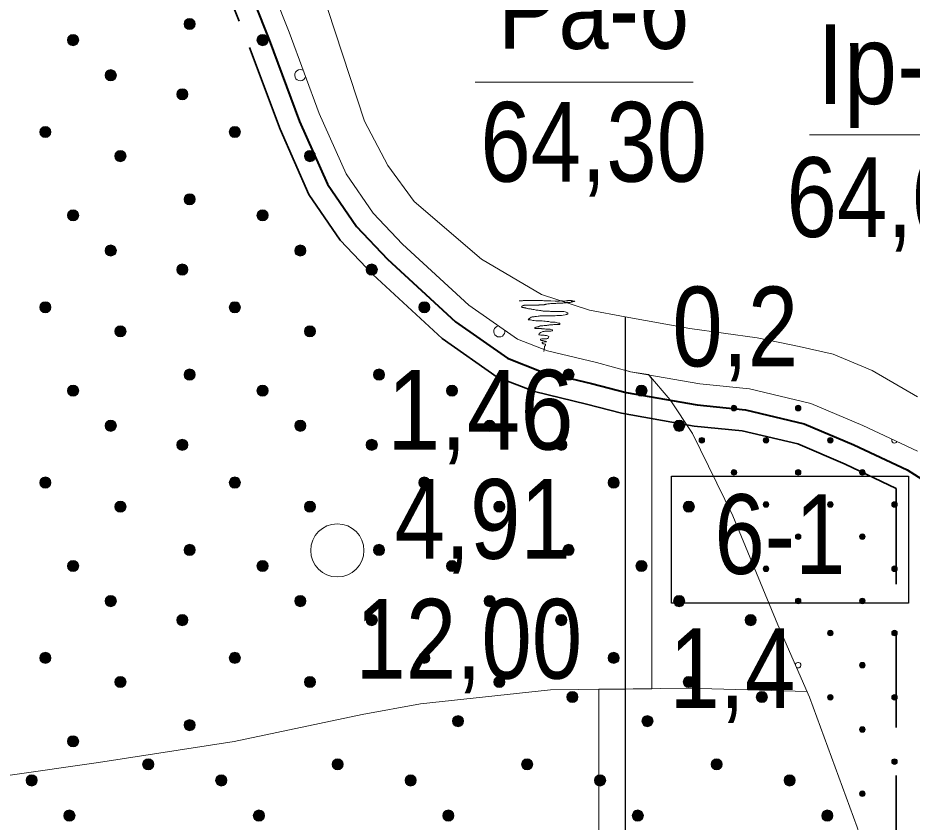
# Model space of a CAD drawing. Extents: x 640121 to 640955, y 6441885 to 6442246.
# Drawn here: x 640239.34 to 640273.01, y 6441962.4 to 6441992.66 of the extents above; entities that cross this region are included whole.
import ezdxf
from ezdxf.enums import TextEntityAlignment as Align

# ---------------------------------------------------------------- set-up
doc = ezdxf.new("R2010")
doc.units = 0
doc.header["$LTSCALE"] = 1.2
doc.linetypes.add('MEDIUM_DASHED', pattern=[4.5, 3, -1.5])
for name, color, linetype, lineweight in [('31', 7, 'Continuous', 13), ('32', 7, 'Continuous', 13), ('33', 7, 'Continuous', 13), ('35', 7, 'Continuous', 35), ('40', 7, 'Continuous', 13), ('44', 7, 'Continuous', 13), ('45', 7, 'Continuous', 13), ('47', 7, 'Continuous', 13)]:
    doc.layers.add(name, color=color, linetype=linetype, lineweight=lineweight)

msp = doc.modelspace()

# ---------------------------------------------------------------- hatches: boundary and pattern name
at = {"layer": '44'}
for points in [[(640246.016, 6441992.434, 1), (640245.596, 6441992.434, 1)], [(640241.63, 6441991.828, 1), (640241.21, 6441991.828, 1)], [(640248.763, 6441991.828, 1), (640248.343, 6441991.828, 1)], [(640243.049, 6441990.506, 1), (640242.629, 6441990.506, 1)], [(640245.742, 6441989.79, 1), (640245.322, 6441989.79, 1)], [(640240.586, 6441988.371, 1), (640240.166, 6441988.371, 1)], [(640247.719, 6441988.371, 1), (640247.299, 6441988.371, 1)], [(640243.413, 6441987.463, 1), (640242.993, 6441987.463, 1)], [(640250.546, 6441987.463, 1), (640250.126, 6441987.463, 1)], [(640246.016, 6441985.838, 1), (640245.596, 6441985.838, 1)], [(640241.63, 6441985.232, 1), (640241.21, 6441985.232, 1)], [(640248.763, 6441985.232, 1), (640248.343, 6441985.232, 1)], [(640243.049, 6441983.91, 1), (640242.629, 6441983.91, 1)], [(640250.182, 6441983.91, 1), (640249.762, 6441983.91, 1)], [(640245.742, 6441983.194, 1), (640245.322, 6441983.194, 1)], [(640252.875, 6441983.194, 1), (640252.455, 6441983.194, 1)], [(640240.586, 6441981.775, 1), (640240.166, 6441981.775, 1)], [(640247.719, 6441981.775, 1), (640247.299, 6441981.775, 1)], [(640254.852, 6441981.775, 1), (640254.432, 6441981.775, 1)], [(640243.413, 6441980.867, 1), (640242.993, 6441980.867, 1)], [(640250.546, 6441980.867, 1), (640250.126, 6441980.867, 1)], [(640246.016, 6441979.242, 1), (640245.596, 6441979.242, 1)], [(640253.149, 6441979.242, 1), (640252.729, 6441979.242, 1)], [(640260.282, 6441979.242, 1), (640259.862, 6441979.242, 1)], [(640241.63, 6441978.636, 1), (640241.21, 6441978.636, 1)], [(640248.763, 6441978.636, 1), (640248.343, 6441978.636, 1)], [(640255.896, 6441978.636, 1), (640255.476, 6441978.636, 1)], [(640263.029, 6441978.636, 1), (640262.609, 6441978.636, 1)], [(640243.049, 6441977.314, 1), (640242.629, 6441977.314, 1)], [(640250.182, 6441977.314, 1), (640249.762, 6441977.314, 1)], [(640257.315, 6441977.314, 1), (640256.895, 6441977.314, 1)], [(640264.448, 6441977.314, 1), (640264.028, 6441977.314, 1)], [(640245.742, 6441976.598, 1), (640245.322, 6441976.598, 1)], [(640252.875, 6441976.598, 1), (640252.455, 6441976.598, 1)], [(640260.008, 6441976.598, 1), (640259.588, 6441976.598, 1)], [(640240.586, 6441975.179, 1), (640240.166, 6441975.179, 1)], [(640247.719, 6441975.179, 1), (640247.299, 6441975.179, 1)], [(640254.852, 6441975.179, 1), (640254.432, 6441975.179, 1)], [(640261.985, 6441975.179, 1), (640261.565, 6441975.179, 1)], [(640243.413, 6441974.271, 1), (640242.993, 6441974.271, 1)], [(640250.546, 6441974.271, 1), (640250.126, 6441974.271, 1)], [(640257.679, 6441974.271, 1), (640257.259, 6441974.271, 1)], [(640264.812, 6441974.271, 1), (640264.392, 6441974.271, 1)], [(640246.016, 6441972.646, 1), (640245.596, 6441972.646, 1)], [(640253.149, 6441972.646, 1), (640252.729, 6441972.646, 1)], [(640260.282, 6441972.646, 1), (640259.862, 6441972.646, 1)], [(640241.63, 6441972.04, 1), (640241.21, 6441972.04, 1)], [(640248.763, 6441972.04, 1), (640248.343, 6441972.04, 1)], [(640255.896, 6441972.04, 1), (640255.476, 6441972.04, 1)], [(640263.029, 6441972.04, 1), (640262.609, 6441972.04, 1)], [(640243.049, 6441970.718, 1), (640242.629, 6441970.718, 1)], [(640250.182, 6441970.718, 1), (640249.762, 6441970.718, 1)], [(640257.315, 6441970.718, 1), (640256.895, 6441970.718, 1)], [(640264.448, 6441970.718, 1), (640264.028, 6441970.718, 1)], [(640245.742, 6441970.002, 1), (640245.322, 6441970.002, 1)], [(640252.875, 6441970.002, 1), (640252.455, 6441970.002, 1)], [(640260.008, 6441970.002, 1), (640259.588, 6441970.002, 1)], [(640267.141, 6441970.002, 1), (640266.721, 6441970.002, 1)], [(640240.586, 6441968.583, 1), (640240.166, 6441968.583, 1)], [(640247.719, 6441968.583, 1), (640247.299, 6441968.583, 1)], [(640254.852, 6441968.583, 1), (640254.432, 6441968.583, 1)], [(640261.985, 6441968.583, 1), (640261.565, 6441968.583, 1)], [(640243.413, 6441967.675, 1), (640242.993, 6441967.675, 1)], [(640250.546, 6441967.675, 1), (640250.126, 6441967.675, 1)], [(640257.679, 6441967.675, 1), (640257.259, 6441967.675, 1)], [(640264.812, 6441967.675, 1), (640264.392, 6441967.675, 1)], [(640260.428, 6441967.109, 1), (640260.008, 6441967.109, 1)], [(640267.561, 6441967.109, 1), (640267.141, 6441967.109, 1)], [(640256.122, 6441966.201, 1), (640255.702, 6441966.201, 1)], [(640263.255, 6441966.201, 1), (640262.835, 6441966.201, 1)], [(640246.016, 6441966.05, 1), (640245.596, 6441966.05, 1)], [(640241.63, 6441965.444, 1), (640241.21, 6441965.444, 1)], [(640244.459, 6441964.576, 1), (640244.039, 6441964.576, 1)], [(640251.592, 6441964.576, 1), (640251.172, 6441964.576, 1)], [(640258.725, 6441964.576, 1), (640258.305, 6441964.576, 1)], [(640265.858, 6441964.576, 1), (640265.438, 6441964.576, 1)], [(640240.073, 6441963.97, 1), (640239.653, 6441963.97, 1)], [(640247.206, 6441963.97, 1), (640246.786, 6441963.97, 1)], [(640254.339, 6441963.97, 1), (640253.919, 6441963.97, 1)], [(640261.472, 6441963.97, 1), (640261.052, 6441963.97, 1)], [(640268.605, 6441963.97, 1), (640268.185, 6441963.97, 1)], [(640241.492, 6441962.648, 1), (640241.072, 6441962.648, 1)], [(640248.625, 6441962.648, 1), (640248.205, 6441962.648, 1)], [(640255.758, 6441962.648, 1), (640255.338, 6441962.648, 1)], [(640262.891, 6441962.648, 1), (640262.471, 6441962.648, 1)], [(640270.024, 6441962.648, 1), (640269.604, 6441962.648, 1)]]:
    msp.add_hatch(color=256, dxfattribs=at).paths.add_polyline_path(points)
at = {"layer": '45'}
for points in [[(640266.373, 6441978.054, 1), (640266.225, 6441977.905, 1)], [(640268.792, 6441978.054, 1), (640268.643, 6441977.905, 1)], [(640265.164, 6441976.845, 1), (640265.016, 6441976.696, 1)], [(640267.583, 6441976.845, 1), (640267.434, 6441976.696, 1)], [(640270.001, 6441976.845, 1), (640269.852, 6441976.696, 1)], [(640266.373, 6441975.636, 1), (640266.225, 6441975.487, 1)], [(640268.792, 6441975.636, 1), (640268.643, 6441975.487, 1)], [(640271.21, 6441975.636, 1), (640271.061, 6441975.487, 1)], [(640267.583, 6441974.426, 1), (640267.434, 6441974.278, 1)], [(640270.001, 6441974.426, 1), (640269.852, 6441974.278, 1)], [(640272.419, 6441974.426, 1), (640272.271, 6441974.278, 1)], [(640268.792, 6441973.217, 1), (640268.643, 6441973.069, 1)], [(640271.21, 6441973.217, 1), (640271.061, 6441973.069, 1)], [(640267.583, 6441972.008, 1), (640267.434, 6441971.86, 1)], [(640270.001, 6441972.008, 1), (640269.852, 6441971.86, 1)], [(640272.419, 6441972.008, 1), (640272.271, 6441971.86, 1)], [(640268.792, 6441970.799, 1), (640268.643, 6441970.65, 1)], [(640271.21, 6441970.799, 1), (640271.061, 6441970.65, 1)], [(640270.001, 6441969.59, 1), (640269.852, 6441969.441, 1)], [(640272.419, 6441969.59, 1), (640272.271, 6441969.441, 1)], [(640271.21, 6441968.381, 1), (640271.061, 6441968.232, 1)], [(640270.001, 6441967.171, 1), (640269.852, 6441967.023, 1)], [(640272.419, 6441967.171, 1), (640272.271, 6441967.023, 1)], [(640271.21, 6441965.962, 1), (640271.061, 6441965.814, 1)], [(640272.419, 6441964.753, 1), (640272.271, 6441964.605, 1)], [(640271.21, 6441963.544, 1), (640271.061, 6441963.396, 1)]]:
    msp.add_hatch(color=256, dxfattribs=at).paths.add_polyline_path(points)

# ---------------------------------------------------------------- linework, layer by layer
at = {"layer": '31'}
for points in [[(640247.83, 6441996.45), (640249.55, 6441992.13), (640250.69, 6441989.07), (640251.7, 6441986.8), (640252.72, 6441985.31), (640253.82, 6441984.15), (640256.32, 6441981.85), (640258.15, 6441980.57), (640259.28, 6441980.13), (640261.13, 6441979.69), (640262.41, 6441979.35), (640265.02, 6441978.89), (640266.88, 6441978.71), (640269.2, 6441978.15), (640271.15, 6441977.33), (640273.21, 6441976.36)], [(640251.01, 6441992.98), (640252.39, 6441988.78), (640253.27, 6441987.11), (640254.26, 6441985.75), (640256.79, 6441983.58), (640259.06, 6441982.26), (640260.86, 6441981.67), (640262.21, 6441981.41), (640264.64, 6441980.98), (640267.17, 6441980.63), (640268.76, 6441980.3), (640270.04, 6441980.01), (640271.5, 6441979.39), (640273.21, 6441978.41)], [(640279.06, 6441928.41), (640278.87, 6441928.63), (640278.5, 6441929.22), (640278.1, 6441930.16), (640277.77, 6441931.22), (640277.06, 6441933.92), (640275.96, 6441939.13), (640274.35, 6441947.19), (640273.2, 6441954.22), (640271.82, 6441959.4), (640270.94, 6441962.21), (640269.15, 6441967.1), (640267.95, 6441969.83), (640266.26, 6441973.93), (640264.74, 6441977.03), (640263.9, 6441978.29), (640263.08, 6441979.24)], [(640160.01, 6441959.79), (640212.12, 6441961.38), (640223.03, 6441962.4), (640231.14, 6441963.16), (640235.45, 6441963.66), (640242.38, 6441964.64), (640247.49, 6441965.44), (640252.3, 6441966.45), (640254.5, 6441966.85), (640259.39, 6441967.38), (640264.58, 6441967.44), (640269.06, 6441967.32)]]:
    msp.add_lwpolyline(points, dxfattribs=at)
at = {"layer": '32'}
for p, q in [((640256.56, 6441990.24), (640264.77, 6441990.24)), ((640269.15, 6441988.26), (640275.57, 6441988.26))]:
    msp.add_line(p, q, dxfattribs=at)
at = {"layer": '32', "lineweight": 25}
msp.add_line((640262.21, 6441981.41), (640262.21, 6441921.41), dxfattribs=at)
at = {"layer": '33'}
for points in [[(640263.21, 6441967.42), (640263.21, 6441979.08), (640263.08, 6441979.24), (640262.41, 6441979.35), (640262.21, 6441979.41), (640262.21, 6441967.41)], [(640261.21, 6441967.4), (640261.21, 6441926.41), (640262.19, 6441926.41), (640262.19, 6441926.41), (640262.21, 6441926.41), (640262.21, 6441967.41), (640261.72, 6441967.41)]]:
    msp.add_lwpolyline(points, close=True, dxfattribs=at)
at = {"layer": '33', "lineweight": 25}
msp.add_lwpolyline([(640263.95, 6441975.42), (640272.87, 6441975.42), (640272.87, 6441970.64), (640263.95, 6441970.64)], close=True, dxfattribs=at)
at = {"layer": '35', "linetype": 'MEDIUM_DASHED'}
msp.add_line((640272.41, 6441974.96), (640272.41, 6441955.31), dxfattribs=at)
at = {"layer": '35', "lineweight": 40}
msp.add_lwpolyline([(640241.6, 6442009.82), (640243.41, 6442005.66), (640245.54, 6442000.51), (640247.08, 6441996.17), (640248.8, 6441991.84), (640249.95, 6441988.77), (640251, 6441986.41), (640252.09, 6441984.81), (640253.26, 6441983.58), (640255.82, 6441981.23), (640257.77, 6441979.86), (640259.04, 6441979.36), (640260.94, 6441978.91), (640262.24, 6441978.57), (640264.91, 6441978.1), (640266.74, 6441977.92), (640268.95, 6441977.39), (640270.82, 6441976.6), (640272.82, 6441975.66), (640274.69, 6441974.46)], dxfattribs=at)
at = {"layer": '35', "linetype": 'MEDIUM_DASHED'}
msp.add_lwpolyline([(640240.87, 6442009.5), (640242.67, 6442005.35), (640244.79, 6442000.23), (640246.34, 6441995.89), (640248.06, 6441991.55), (640249.21, 6441988.47), (640250.3, 6441986.02), (640251.47, 6441984.3), (640252.7, 6441983.01), (640255.32, 6441980.6), (640257.39, 6441979.15), (640258.79, 6441978.6), (640260.75, 6441978.13), (640262.07, 6441977.79), (640264.8, 6441977.3), (640266.61, 6441977.13), (640268.7, 6441976.63), (640270.49, 6441975.87), (640272.41, 6441974.96)], dxfattribs=at)
at = {"layer": '40'}
for points in [[(640258.21, 6441982.02), (640258.24, 6441982.02), (640258.29, 6441982.02), (640258.34, 6441982.02), (640258.36, 6441982.03), (640258.41, 6441982.03), (640258.49, 6441982.03), (640258.65, 6441982.03), (640258.74, 6441982.03), (640258.76, 6441982.03), (640258.78, 6441982.03), (640258.81, 6441982.03), (640258.85, 6441982.03), (640258.91, 6441982.03), (640258.95, 6441982.03), (640258.98, 6441982.03), (640259.02, 6441982.03), (640259.06, 6441982.03), (640259.09, 6441982.03), (640259.14, 6441982.02), (640259.16, 6441982.02), (640259.2, 6441982.02), (640259.24, 6441982.02), (640259.41, 6441982.02), (640259.57, 6441982.01), (640259.62, 6441982.01), (640259.65, 6441982.01), (640259.66, 6441982.01), (640259.69, 6441982.01), (640259.72, 6441982.01), (640259.77, 6441982.02), (640259.8, 6441982.02), (640259.81, 6441982.02), (640259.83, 6441982.02), (640259.84, 6441982.02), (640259.88, 6441982.01), (640259.9, 6441982.01), (640259.92, 6441982.01), (640259.97, 6441982.02), (640260, 6441982.02), (640260.04, 6441982.02), (640260.05, 6441982.03), (640260.09, 6441982.03), (640260.11, 6441982.03), (640260.13, 6441982.03), (640260.16, 6441982.03), (640260.17, 6441982.03), (640260.19, 6441982.02), (640260.22, 6441982.02), (640260.23, 6441982.02)], [(640260.23, 6441982.02), (640260.26, 6441982.01), (640260.28, 6441982.01), (640260.3, 6441982.01), (640260.31, 6441982), (640260.3, 6441981.99), (640260.31, 6441982), (640260.29, 6441981.99), (640260.26, 6441981.99), (640260.23, 6441981.98), (640260.22, 6441981.98), (640260.19, 6441981.98), (640260.17, 6441981.97), (640260.16, 6441981.97), (640260.14, 6441981.96), (640260.11, 6441981.96), (640260.08, 6441981.96), (640260.06, 6441981.96), (640260, 6441981.95), (640259.98, 6441981.94), (640259.96, 6441981.94), (640259.93, 6441981.94), (640259.91, 6441981.94), (640259.89, 6441981.94), (640259.86, 6441981.93), (640259.84, 6441981.93), (640259.79, 6441981.93), (640259.76, 6441981.93), (640259.72, 6441981.93), (640259.68, 6441981.93), (640259.65, 6441981.93), (640259.63, 6441981.93), (640259.6, 6441981.92), (640259.57, 6441981.92), (640259.48, 6441981.92), (640259.47, 6441981.92), (640259.45, 6441981.91), (640259.41, 6441981.91), (640259.36, 6441981.9), (640259.32, 6441981.9), (640259.29, 6441981.9), (640259.25, 6441981.89), (640259.22, 6441981.89), (640259.2, 6441981.88), (640259.17, 6441981.88), (640259.15, 6441981.87), (640259.14, 6441981.87), (640259.11, 6441981.87), (640259.08, 6441981.87), (640259.06, 6441981.87), (640259, 6441981.86), (640258.97, 6441981.86)], [(640258.97, 6441981.86), (640258.96, 6441981.85), (640258.93, 6441981.85), (640258.91, 6441981.85), (640258.89, 6441981.85), (640258.87, 6441981.85), (640258.85, 6441981.85), (640258.82, 6441981.85), (640258.8, 6441981.85), (640258.76, 6441981.85), (640258.75, 6441981.85), (640258.72, 6441981.85), (640258.7, 6441981.85), (640258.68, 6441981.85), (640258.66, 6441981.85), (640258.64, 6441981.85), (640258.61, 6441981.85), (640258.58, 6441981.85), (640258.56, 6441981.85), (640258.54, 6441981.85), (640258.51, 6441981.85), (640258.49, 6441981.85), (640258.47, 6441981.85), (640258.45, 6441981.85), (640258.43, 6441981.85), (640258.4, 6441981.85), (640258.39, 6441981.84), (640258.36, 6441981.84), (640258.34, 6441981.83), (640258.33, 6441981.82), (640258.32, 6441981.82), (640258.31, 6441981.81), (640258.3, 6441981.79), (640258.31, 6441981.77), (640258.36, 6441981.76), (640258.39, 6441981.76), (640258.4, 6441981.75), (640258.43, 6441981.75), (640258.45, 6441981.75), (640258.46, 6441981.74), (640258.49, 6441981.74), (640258.51, 6441981.73), (640258.53, 6441981.73), (640258.57, 6441981.72), (640258.6, 6441981.71), (640258.64, 6441981.71), (640258.66, 6441981.7), (640258.69, 6441981.7), (640258.73, 6441981.69), (640258.78, 6441981.69)], [(640258.78, 6441981.69), (640258.85, 6441981.67), (640258.9, 6441981.66), (640258.93, 6441981.66), (640258.98, 6441981.65), (640259.03, 6441981.65), (640259.06, 6441981.64), (640259.09, 6441981.64), (640259.12, 6441981.63), (640259.16, 6441981.63), (640259.19, 6441981.63), (640259.23, 6441981.63), (640259.27, 6441981.63), (640259.31, 6441981.63), (640259.36, 6441981.63), (640259.4, 6441981.62), (640259.43, 6441981.62), (640259.45, 6441981.62), (640259.48, 6441981.62), (640259.52, 6441981.62), (640259.56, 6441981.62), (640259.61, 6441981.62), (640259.65, 6441981.62), (640259.68, 6441981.62), (640259.72, 6441981.62), (640259.74, 6441981.62), (640259.77, 6441981.62), (640259.8, 6441981.62), (640259.83, 6441981.61), (640259.86, 6441981.61), (640259.89, 6441981.61), (640259.95, 6441981.6), (640259.98, 6441981.59), (640260.01, 6441981.58), (640260.04, 6441981.57), (640260.05, 6441981.57), (640260.05, 6441981.55), (640260.05, 6441981.53), (640260.04, 6441981.52), (640260.02, 6441981.52), (640260.01, 6441981.51), (640259.99, 6441981.5), (640259.95, 6441981.49), (640259.87, 6441981.48), (640259.81, 6441981.47), (640259.77, 6441981.46), (640259.72, 6441981.46), (640259.68, 6441981.46), (640259.63, 6441981.46), (640259.57, 6441981.45), (640259.47, 6441981.45), (640259.39, 6441981.45)], [(640259.39, 6441981.45), (640259.35, 6441981.45), (640259.31, 6441981.45), (640259.27, 6441981.45), (640259.24, 6441981.45), (640259.21, 6441981.45), (640259.17, 6441981.45), (640259.12, 6441981.45), (640259.03, 6441981.45), (640258.99, 6441981.45), (640258.97, 6441981.44), (640258.93, 6441981.44), (640258.87, 6441981.43), (640258.8, 6441981.43), (640258.78, 6441981.42), (640258.75, 6441981.42), (640258.73, 6441981.42), (640258.72, 6441981.41), (640258.7, 6441981.41), (640258.68, 6441981.4), (640258.66, 6441981.4), (640258.65, 6441981.39), (640258.62, 6441981.37), (640258.6, 6441981.36), (640258.6, 6441981.34), (640258.58, 6441981.34), (640258.57, 6441981.33), (640258.56, 6441981.31), (640258.55, 6441981.3), (640258.57, 6441981.3), (640258.58, 6441981.3), (640258.61, 6441981.3), (640258.64, 6441981.3), (640258.69, 6441981.29), (640258.73, 6441981.28), (640258.78, 6441981.28), (640258.84, 6441981.27), (640258.87, 6441981.27), (640258.9, 6441981.26), (640258.93, 6441981.26), (640259.02, 6441981.26), (640259.08, 6441981.26), (640259.14, 6441981.25), (640259.19, 6441981.25), (640259.26, 6441981.24), (640259.33, 6441981.24), (640259.39, 6441981.22), (640259.44, 6441981.22), (640259.48, 6441981.22), (640259.53, 6441981.22)], [(640259.53, 6441981.22), (640259.55, 6441981.22), (640259.57, 6441981.21), (640259.62, 6441981.2), (640259.65, 6441981.19), (640259.68, 6441981.18), (640259.7, 6441981.18), (640259.73, 6441981.17), (640259.74, 6441981.16), (640259.75, 6441981.14), (640259.74, 6441981.13), (640259.72, 6441981.13), (640259.71, 6441981.12), (640259.65, 6441981.12), (640259.62, 6441981.12), (640259.6, 6441981.12), (640259.56, 6441981.12), (640259.52, 6441981.12), (640259.48, 6441981.11), (640259.45, 6441981.11), (640259.43, 6441981.11), (640259.36, 6441981.11), (640259.33, 6441981.1), (640259.31, 6441981.1), (640259.28, 6441981.1), (640259.26, 6441981.09), (640259.23, 6441981.09), (640259.19, 6441981.09), (640259.15, 6441981.09), (640259.11, 6441981.08), (640259.08, 6441981.07), (640259.06, 6441981.07), (640259.04, 6441981.07), (640259.02, 6441981.07), (640258.99, 6441981.07), (640258.99, 6441981.06), (640258.96, 6441981.05), (640258.94, 6441981.04), (640258.93, 6441981.04), (640258.9, 6441981.04), (640258.87, 6441981.03), (640258.84, 6441981.03), (640258.82, 6441981.01), (640258.81, 6441981), (640258.81, 6441980.98), (640258.82, 6441980.98), (640258.86, 6441980.98), (640258.91, 6441980.97), (640258.95, 6441980.97), (640258.97, 6441980.97), (640259.02, 6441980.97), (640259.05, 6441980.97)], [(640259.05, 6441980.97), (640259.06, 6441980.96), (640259.08, 6441980.96), (640259.11, 6441980.96), (640259.15, 6441980.96), (640259.17, 6441980.96), (640259.22, 6441980.95), (640259.26, 6441980.95), (640259.28, 6441980.95), (640259.3, 6441980.95), (640259.32, 6441980.95), (640259.35, 6441980.95), (640259.38, 6441980.95), (640259.41, 6441980.94), (640259.43, 6441980.93), (640259.45, 6441980.92), (640259.47, 6441980.92), (640259.47, 6441980.89), (640259.41, 6441980.88), (640259.33, 6441980.88), (640259.3, 6441980.88), (640259.25, 6441980.87), (640259.22, 6441980.87), (640259.18, 6441980.87), (640259.15, 6441980.86), (640259.11, 6441980.86), (640259.08, 6441980.85), (640259.03, 6441980.83), (640259.02, 6441980.82), (640259, 6441980.81), (640258.99, 6441980.8), (640258.97, 6441980.79), (640258.97, 6441980.77), (640258.96, 6441980.75), (640258.97, 6441980.74), (640258.99, 6441980.74), (640259.03, 6441980.73), (640259.09, 6441980.73), (640259.15, 6441980.72), (640259.18, 6441980.71), (640259.2, 6441980.71), (640259.24, 6441980.71), (640259.28, 6441980.7), (640259.33, 6441980.68), (640259.33, 6441980.66), (640259.32, 6441980.64), (640259.32, 6441980.63), (640259.28, 6441980.6), (640259.26, 6441980.59), (640259.23, 6441980.59), (640259.19, 6441980.59), (640259.15, 6441980.59), (640259.11, 6441980.59), (640259.07, 6441980.59), (640259.03, 6441980.58), (640259.02, 6441980.56), (640259.02, 6441980.55), (640259.02, 6441980.54), (640259.04, 6441980.53), (640259.1, 6441980.52), (640259.14, 6441980.51), (640259.17, 6441980.5), (640259.2, 6441980.5), (640259.23, 6441980.49), (640259.24, 6441980.48), (640259.23, 6441980.47), (640259.2, 6441980.47), (640259.17, 6441980.47), (640259.12, 6441980.46), (640259.1, 6441980.46), (640259.08, 6441980.46), (640259.08, 6441980.43), (640259.09, 6441980.42), (640259.11, 6441980.41), (640259.12, 6441980.4), (640259.15, 6441980.4), (640259.18, 6441980.39), (640259.2, 6441980.38), (640259.21, 6441980.36), (640259.2, 6441980.35), (640259.19, 6441980.33), (640259.18, 6441980.31), (640259.17, 6441980.3), (640259.17, 6441980.28), (640259.17, 6441980.25), (640259.17, 6441980.23), (640259.16, 6441980.22), (640259.16, 6441980.19), (640259.15, 6441980.18), (640259.15, 6441980.16), (640259.14, 6441980.14), (640259.14, 6441980.11), (640259.14, 6441980.11), (640259.14, 6441980.13)]]:
    msp.add_lwpolyline(points, dxfattribs=at)
at = {"layer": '44'}
for centre in [(640245.806, 6441992.434), (640241.42, 6441991.828), (640248.553, 6441991.828), (640242.839, 6441990.506), (640245.532, 6441989.79), (640240.376, 6441988.371), (640247.509, 6441988.371), (640243.203, 6441987.463), (640250.336, 6441987.463), (640245.806, 6441985.838), (640241.42, 6441985.232), (640248.553, 6441985.232), (640242.839, 6441983.91), (640249.972, 6441983.91), (640245.532, 6441983.194), (640252.665, 6441983.194), (640240.376, 6441981.775), (640247.509, 6441981.775), (640254.642, 6441981.775), (640243.203, 6441980.867), (640250.336, 6441980.867), (640245.806, 6441979.242), (640252.939, 6441979.242), (640260.072, 6441979.242), (640241.42, 6441978.636), (640248.553, 6441978.636), (640255.686, 6441978.636), (640262.819, 6441978.636), (640242.839, 6441977.314), (640249.972, 6441977.314), (640257.105, 6441977.314), (640264.238, 6441977.314), (640245.532, 6441976.598), (640252.665, 6441976.598), (640259.798, 6441976.598), (640240.376, 6441975.179), (640247.509, 6441975.179), (640254.642, 6441975.179), (640261.775, 6441975.179), (640243.203, 6441974.271), (640250.336, 6441974.271), (640257.469, 6441974.271), (640264.602, 6441974.271), (640245.806, 6441972.646), (640252.939, 6441972.646), (640260.072, 6441972.646), (640241.42, 6441972.04), (640248.553, 6441972.04), (640255.686, 6441972.04), (640262.819, 6441972.04), (640242.839, 6441970.718), (640249.972, 6441970.718), (640257.105, 6441970.718), (640264.238, 6441970.718), (640245.532, 6441970.002), (640252.665, 6441970.002), (640259.798, 6441970.002), (640266.931, 6441970.002), (640240.376, 6441968.583), (640247.509, 6441968.583), (640254.642, 6441968.583), (640261.775, 6441968.583), (640243.203, 6441967.675), (640250.336, 6441967.675), (640257.469, 6441967.675), (640264.602, 6441967.675), (640260.218, 6441967.109), (640267.351, 6441967.109), (640255.912, 6441966.201), (640263.045, 6441966.201), (640245.806, 6441966.05), (640241.42, 6441965.444), (640244.249, 6441964.576), (640251.382, 6441964.576), (640258.515, 6441964.576), (640265.648, 6441964.576), (640239.863, 6441963.97), (640246.996, 6441963.97), (640254.129, 6441963.97), (640261.262, 6441963.97), (640268.395, 6441963.97), (640241.282, 6441962.648), (640248.415, 6441962.648), (640255.548, 6441962.648), (640262.681, 6441962.648), (640269.814, 6441962.648)]:
    msp.add_circle(centre, 0.21, dxfattribs=at)
for centre, start, end in [((640249.972, 6441990.506), 54.9868, 346.0013), ((640257.469, 6441980.867), 99.6275, 10.4305)]:
    msp.add_arc(centre, 0.21, start, end, dxfattribs=at)
at = {"layer": '45'}
for centre in [(640266.299, 6441977.98), (640268.717, 6441977.98), (640265.09, 6441976.77), (640267.508, 6441976.77), (640269.927, 6441976.77), (640266.299, 6441975.561), (640268.717, 6441975.561), (640271.136, 6441975.561), (640267.508, 6441974.352), (640269.927, 6441974.352), (640272.345, 6441974.352), (640268.717, 6441973.143), (640271.136, 6441973.143), (640267.508, 6441971.934), (640269.927, 6441971.934), (640272.345, 6441971.934), (640268.717, 6441970.725), (640271.136, 6441970.725), (640269.927, 6441969.516), (640272.345, 6441969.516), (640271.136, 6441968.306), (640269.927, 6441967.097), (640272.345, 6441967.097), (640271.136, 6441965.888), (640272.345, 6441964.679), (640271.136, 6441963.47)]:
    msp.add_circle(centre, 0.105, dxfattribs=at)
for centre, start, end in [((640272.345, 6441976.77), 157.7554, 331.7636), ((640268.717, 6441968.306), 236.2273, 171.493)]:
    msp.add_arc(centre, 0.105, start, end, dxfattribs=at)
at = {"layer": '47'}
msp.add_circle((640251.368, 6441972.626), 1, dxfattribs=at)

# ---------------------------------------------------------------- texts
at = {"layer": '32'}
for s, width, p in [('Pa-6', 0.85, (640261.02, 6441991.5)), ('Ip-3', 0.9, (640272.545, 6441989.42)), ('64,30', 0.85, (640261.02, 6441986.5)), ('64,00', 0.85, (640272.545, 6441984.42)), ('0,2', 0.85, (640266.35, 6441979.55)), ('1,46', 0.9, (640256.75, 6441976.42)), ('4,91', 0.85, (640256.84, 6441972.31)), ('12,00', 0.85, (640256.32, 6441967.8)), ('1,4', 0.85, (640266.24, 6441966.69))]:
    msp.add_text(s, height=3, dxfattribs=dict(at, width=width)).set_placement(p, align=Align.CENTER)
at = {"layer": '33', "width": 0.85}
msp.add_text('6-1', height=3, dxfattribs=at).set_placement((640268.03, 6441971.74), align=Align.CENTER)

doc.saveas('drawing.dxf')
